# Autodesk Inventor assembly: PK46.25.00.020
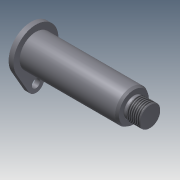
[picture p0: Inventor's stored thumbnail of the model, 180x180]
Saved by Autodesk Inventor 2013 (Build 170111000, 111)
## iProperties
Created: 2005-05
Part Number: PK46.25.00.020
Document SubType Name: Assembly
Designer: PVitaliy
Manufacturer: Standard
Standards Organization: Custom
Author: PVitaliy
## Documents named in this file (3)
- D:\FrontLoaderVault\Data\Assy, Chassis, Front\PK46.25.00.020.iam
- D:\FrontLoaderVault\Data\Assy, Chassis, Front\PK46.25.00.003.ipt
- D:\FrontLoaderVault\Data\Assy, Chassis, Front\PK46.25.00.002.ipt
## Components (2 placed, 2 different names)
1. PK46.25.00.003:1 — Insert:1
2. PK46.25.00.002:1 — Insert:1, Mate:1
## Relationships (2: Insert 1, Mate 1)
- Insert:1: PK46.25.00.003:1 ↔ PK46.25.00.002:1
- Mate:1: PK46.25.00.002:1
